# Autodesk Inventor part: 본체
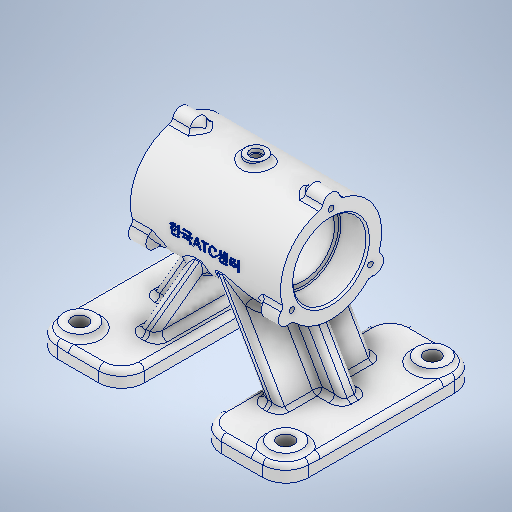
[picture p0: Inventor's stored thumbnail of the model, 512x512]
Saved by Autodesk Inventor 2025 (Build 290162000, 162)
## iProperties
Created: 2026-04
Part Number: 본체
Material: 알루미늄 6061
Document SubType Name: Modeling
Designer: KDI
Density: 2.7 g/cm^3
Appearance: 알루미늄 - 평지
Mass: 744.03 g
Surface Area: 671.494 cm^2
Volume: 275.567 cm^3
Author: KDI
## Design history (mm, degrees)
sketch "스케치1"
  geometry: L1 (-49.679, 0)-(37.321, 0); L2 (-43, 0)-(-43, 29); L3 (-43, 29)-(0, 29); L4 (-43, 21)-(-27.6, 21); L5 (-27, 20.4)-(-27, 18); L6 (-27, 18)-(0, 18); L7 (0, 0)-(0, 69.66); L8 (43, 0)-(43, 29); L9 (43, 29)-(0, 29); L10 (43, 21)-(27.6, 21); L11 (27, 20.4)-(27, 18); L12 (27, 18)-(0, 18); A1 r 0.6 centre (-27.6, 20.4) between (-27, 20.4) and (-27.6, 21); A2 r 0.6 centre (27.6, 20.4) between (27.6, 21) and (27, 20.4); 4 further points
  constraints: 24 end point, 7 point on line, 6 symmetric about line, 4 perpendicular, 4 point on circle, 4 tangent, 2 centre point, 2 vertical, 1 equal radius, 1 horizontal, 1 horizontal alignment, 1 midpoint
  dimensions: "d0" = 58 diameter of L3 L1; "d1" = 42 diameter of point (-35.3, 21) L1; "d2" = 36 diameter of L6 L1; "d3" = 43 distance between parallel lines of L7 L2; "d4" = 16 distance of L4.start point (-27, 21); "d77" = 0.6 radius of A1
revolve "회전1" sketch "스케치1" stored, may be unused: angle "d5" = 90 deg
sketch "스케치2"
  geometry: L1 (-43, -29)-(43, -29) reference; L2 (-30.845, -21)-(-55.094, -63); L3 (-55.094, -63)-(-72, -63); L4 (-72, -63)-(-72, -72); L5 (-72, -72)-(-22, -72); L6 (-22, -72)-(-22, -63); L7 (-22, -63)-(-32, -63); L8 (-32, -63)-(-7.751, -21); L9 (0, 47.304)-(0, -130.656); L10 (30.845, -21)-(55.094, -63); L11 (55.094, -63)-(72, -63); L12 (72, -63)-(72, -72); L13 (72, -72)-(22, -72); L14 (22, -72)-(22, -63); L15 (22, -63)-(32, -63); L16 (32, -63)-(7.751, -21); L17 (-55.094, -63)-(-32, -63); L18 (-16.989, -21)-(-42.392, -65); L19 (16.989, -21)-(42.392, -65); L20 (32, -63)-(55.094, -63); L21 (-43, -21)-(-43, 21) reference; L22 (43, -21)-(43, 21) reference; L23 (-43, -21)-(43, -21); L24 (-43, -21)-(43, -21); 18 further points
  constraints: 42 end point, 19 point on line, 10 symmetric about line, 3 horizontal, 3 parallel, 3 perpendicular, 1 vertical, 1 vertical alignment
  dimensions: "d6" = 50 distance of L4.end L5.end; "d7" = 10 distance of L6.end L7.end; "d8" = 9 distance of L5.end L6.end; "d9" = 44 distance between parallel lines of L14 L6; "d10" = 60 deg angle of L16 L8; "d11" = 72 distance from line of L5 point (0, 0); "d12" = 8 distance between parallel lines of L18 L8; "d13" = 12 distance between parallel lines of L18 L2; "d90" = 10 distance of L14.end L15.end (derived)
extrude "돌출1" join sketch "스케치2" stored distance "d14" = 110; taper "d15" = 0 deg
extrude "돌출2" join sketch "스케치2" stored distance "d16" = 10; taper "d17" = 0 deg
extrude "돌출3" join sketch "스케치2" stored distance "d18" = 54; taper "d19" = 0 deg
feature "면 삭제1"
feature "면 삭제2"
sketch "스케치7"
  geometry: C1 r 9 at (13, -13); C2 r 9 at (131, -13); C3 r 9 at (13, -97); C4 r 9 at (131, -97); C5 r 4.5 at (13, -13); C6 r 4.5 at (131, -13); C7 r 4.5 at (131, -97); C8 r 4.5 at (13, -97); 1 further point
  constraints: 8 centre point, 4 coincident, 3 equal radius, 2 horizontal alignment, 2 vertical alignment
  dimensions: "d20" = 18 diameter of C1; "d21" = 118 distance of C2.centre C1.centre; "d22" = 59 horizontal distance of point (72, -55) C1.centre (= 0.5 x d21); "d23" = 84 distance of C3.centre C1.centre; "d24" = 42 vertical distance of point (72, -55) C1.centre (= 0.5 x d23); "d25" = 9 diameter of C5; "d26" = 9 diameter of C6; "d27" = 9 diameter of C7; "d28" = 9 diameter of C8
extrude "돌출4" join sketch "스케치7" distance "d29" = 3; taper "d30" = 0 deg
extrude "돌출5" cut sketch "스케치7" extent not by distance; stored distance "d31" = 0; taper "d32" = 0 deg
node "작업 평면1"
sketch "스케치8"
  geometry: C1 r 6 at (0, 0); 1 further point
  constraints: 1 centre point, 1 coincident
  dimensions: "d34" = 12 diameter of C1
extrude "돌출6" join sketch "스케치8" stored distance "d35" = 3; taper "d36" = 0 deg
sketch "스케치10"
  geometry: L1 (-43, 29)-(43, 29) reference; L2 (43, 29)-(43, 34); L3 (43, 34)-(33, 34); L4 (33, 34)-(28, 29); L5 (-43, 29)-(-43, 34); L6 (-43, 34)-(-33, 34); L7 (-33, 34)-(-28, 29); L8 (72, -72)-(22, -72) reference; 1 further point
  constraints: 12 end point, 4 perpendicular, 3 point on line, 1 vertical
  dimensions: "d47" = 90 deg angle of L7 L4; "d48" = 10 distance of L2.end L3.end; "d49" = 10 distance of L5.end L6.end; "d50" = 106 distance between parallel lines of L8 L3
revolve "회전2" sketch "스케치10" stored, may be unused: angle "d51" = 360 deg
sketch "스케치11" dims "d55" = 52
  geometry: A1 r 29 centre (0, -29) between (27.232, -38.97) and (4.981, -0.431) reference; 3 further points
  constraints: 2 vertical alignment, 1 coincident, 2 other
hole "구멍1" sketch "스케치11" at (0, -3) diameter "d56" = 3.242; stored, may be unused: countersink angle "d60" = 90 deg, drill point angle "d62" = 118 deg; dims "d57" = 8, "d58" = 4, "d59" = 2, "d61" = 10
sketch "스케치12"
  geometry: 2 further points
  constraints: 1 coincident
hole "구멍2" sketch "스케치12" at (0, 0) diameter "d66" = 5.1881; stored, may be unused: countersink angle "d70" = 90 deg, drill point angle "d72" = 0 deg; dims "d67" = 20, "d68" = 7, "d69" = 2, "d71" = 10
fillet "모깎기1" dims "d73" = 13
sketch "스케치13"
  geometry: 3 further points
  constraints: 1 coincident, 1 other
  dimensions: "d74" = 72 horizontal distance of point (72, -72) point (0, 0)
feature "엠보싱1" sketch "스케치13" dims "d6" = 50, "d7" = 10, "d8" = 9, "d9" = 44, "d10" = 60 deg, "d11" = 72, "d12" = 8, "d13" = 12, "d75" = 0.5, "d76" = 0, "d90" = 10 (derived)
chamfer "모따기1" distance "d78" = 1; stored, may be unused: second distance "d79" = 2, angle "d80" = 45 deg
fillet "모깎기2" dims "d81" = 3
fillet "모깎기3" dims "d82" = 3
fillet "모깎기4" dims "d83" = 3
fillet "모깎기5" dims "d84" = 3
fillet "모깎기6" dims "d85" = 3
node "솔리드1"
mirror "미러1"
pattern_circular "원형 패턴1" dims angle "d53" = 360 deg
pattern_circular "원형 패턴2" dims angle "d64" = 360 deg
mirror "미러2"
mirror "미러3"
feature "A9D066F2-1C7D-4E18-AEED-F7BC21143FA4" dims "d66" = 5.1881, "d67" = 20, "d68" = 7, "d69" = 2, "d70" = 90 deg, "d71" = 10, "d72" = 0
other parameters: "d33" = 32
